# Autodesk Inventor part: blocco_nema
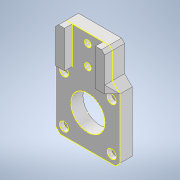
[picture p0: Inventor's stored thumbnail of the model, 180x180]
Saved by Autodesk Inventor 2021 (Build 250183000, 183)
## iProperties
Created: 2026-01
Part Number: blocco_nema
Material: Generico
Document SubType Name: Modeling
Designer: hp
Density: 1 g/cm^3
Appearance: Default
Author: hp
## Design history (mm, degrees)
feature "Solido1"
sketch "Sketch1"
  geometry: L1 (7.95, 42)-(-2.99, 42) reference; L2 (-2.99, 42.01)-(-2.99, 42) reference; L3 (-2.99, 42.01)-(-3, 42) reference; L4 (-3, 42)-(-3, 3) reference; L5 (0, 0)-(-3, 3) reference; L6 (0, 0)-(36, 0) reference; L7 (39, 3)-(36, 0) reference; L8 (39, 3)-(39, 42) reference; L9 (38.99, 42.01)-(39, 42) reference; L10 (38.99, 42)-(38.99, 42.01) reference; L11 (38.99, 42)-(28.05, 42) reference; L12 (28.05, 66)-(28.05, 42) reference; L13 (28.05, 66)-(7.95, 66) reference; L14 (7.95, 42)-(7.95, 66) reference; L15 (7.95, 42)-(7.95, 66) reference; L16 (7.95, 66)-(4, 66) reference; L17 (2, 64)-(4, 66) reference; L18 (2, 64)-(2, 42) reference; L19 (2, 42)-(7.95, 42) reference; L20 (28.05, 66)-(28.05, 42) reference; L21 (28.05, 42)-(34, 42) reference; L22 (34, 42)-(34, 64) reference; L23 (32, 66)-(34, 64) reference; L24 (32, 66)-(28.05, 66) reference; L25 (2, 47)-(-2.99, 42.01) reference; L26 (-2.99, 42.01)-(-2.99, 42) reference; L27 (-2.99, 42)-(2, 42) reference; L28 (2, 42)-(2, 47) reference; L29 (38.99, 42.01)-(34, 47) reference; L30 (34, 47)-(34, 42) reference; L31 (34, 42)-(38.99, 42) reference; L32 (38.99, 42)-(38.99, 42.01) reference; C1 r 2.15 at (18, 47) reference; C2 r 2.15 at (18, 60) reference; C3 r 11.1 at (18, 21) reference; C4 r 2.9 at (2.5, 36.5) reference; C5 r 2.9 at (2.5, 5.5) reference; C6 r 2.9 at (33.5, 5.5) reference; C7 r 2.9 at (33.5, 36.5) reference; 1 further point
  node "Projected Loop1"
  node "Projected Loop2"
  node "Projected Loop3"
  node "Projected Loop4"
  node "Projected Loop5"
body "Solid1"
